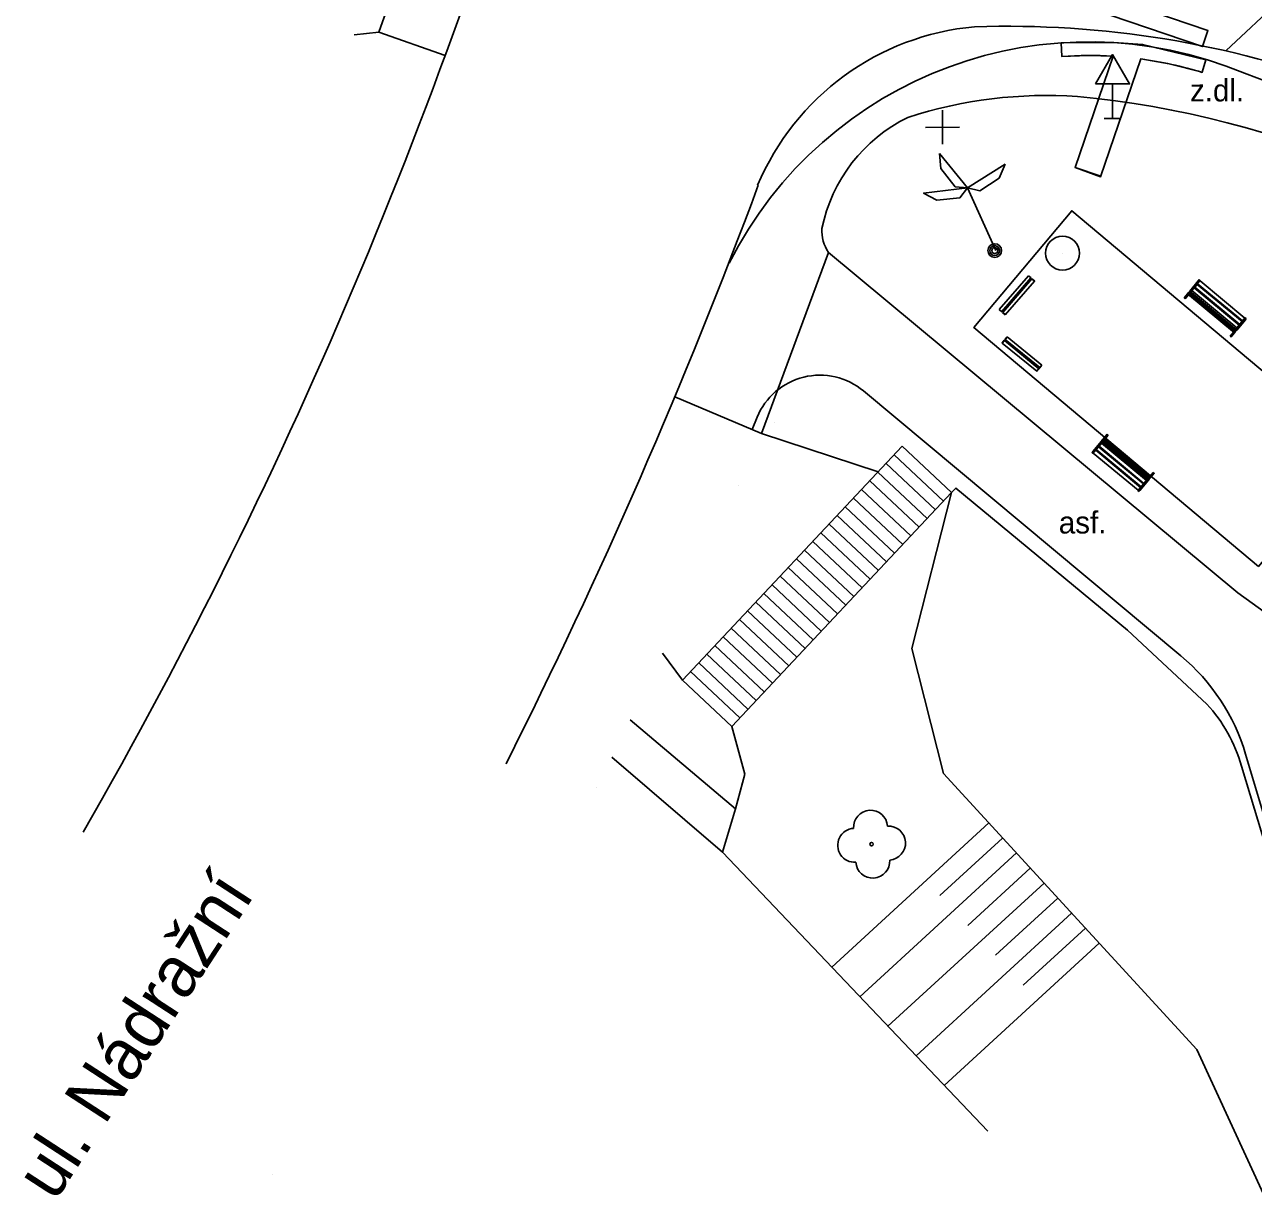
# Model space of a CAD drawing. Extents: x -438303 to -437792, y -1133191 to -1132731.
# Drawn here: x -438176.97 to -438140.8, y -1132981.26 to -1132946.7 of the extents above; entities that cross this region are included whole.
import ezdxf

# ---------------------------------------------------------------- set-up
doc = ezdxf.new("R2010")
doc.units = 0
for name, color, linetype in [('MOBILIÁŘ', 7, 'Continuous'), ('Vrstva 1', 7, 'Continuous'), ('Vrstva 10', 7, 'Continuous'), ('Vrstva 11', 7, 'Continuous'), ('Vrstva 14', 7, 'Continuous'), ('Vrstva 15', 7, 'Continuous'), ('Vrstva 22', 7, 'Continuous'), ('Vrstva 27', 7, 'Continuous'), ('Vrstva 3', 7, 'Continuous'), ('Vrstva 33', 7, 'Continuous'), ('Vrstva 34', 7, 'Continuous'), ('Vrstva 40', 7, 'Continuous'), ('Vrstva 61', 7, 'Continuous')]:
    doc.layers.add(name, color=color, linetype=linetype)

# ---------------------------------------------------------------- blocks, each defined once
blk = doc.blocks.new('A$C6CEF62CF')
at = {"layer": 'Vrstva 1'}
for p, q in [((-6549, 2350), (-6600, 2350)), ((-6600, 2350), (-6600, 2328)), ((-6600, 2328), (-6600, 1317)), ((-6549, 1317), (-6600, 1317)), ((-6600, 15), (-6600, 1026)), ((-6549, 1026), (-6600, 1026)), ((-6600, 0), (-6600, 15)), ((-6549, 0), (-6600, 0)), ((-6549, 2328), (-6549, 2351)), ((-6549, 2350), (6549, 2350)), ((-6549, 2328), (-6549, 1339)), ((-6549, 1375), (6549, 1375)), ((-6549, 1317), (-6549, 1339)), ((-6549, 1317), (6549, 1317)), ((-6549, 1026), (-6549, 1004)), ((-6549, 1026), (6549, 1026)), ((-6549, 15), (-6549, 1004)), ((-6549, 968), (6549, 968)), ((-6549, 15), (-6549, 0)), ((-6549, 0), (6549, 0)), ((-6447, 1317), (-6447, 1026)), ((-6033, 1026), (-6033, 1317)), ((6032, 1317), (6032, 1026)), ((6447, 1026), (6447, 1317)), ((6600, 2350), (6549, 2350)), ((6549, 2350), (6549, 2328)), ((6549, 2328), (6549, 1339)), ((6549, 1339), (6549, 1317)), ((6600, 1317), (6549, 1317)), ((6549, 15), (6549, 1026)), ((6600, 1026), (6549, 1026)), ((6549, 0), (6549, 15)), ((6600, 0), (6549, 0)), ((6600, 2328), (6600, 2351)), ((6600, 2328), (6600, 1339)), ((6600, 1317), (6600, 1339)), ((6600, 1026), (6600, 1004)), ((6600, 15), (6600, 1004)), ((6600, 15), (6600, 0))]:
    blk.add_line(p, q, dxfattribs=at)
blk = doc.blocks.new('A$C6FF56919')
at = {"layer": 'Vrstva 1'}
for p, q in [((-18000, 5423), (-18000, 5482)), ((-18000, 5482), (-17605, 5482)), ((-18000, 5423), (0, 5423)), ((-18000, 5108), (-18000, 5423)), ((-18000, 5108), (0, 5108)), ((-18000, 4771), (-18000, 5108)), ((-18000, 4771), (0, 4771)), ((-18000, 4707), (-18000, 4771)), ((0, 4707), (-18000, 4707)), ((-18000, 4707), (-18000, 4365)), ((-18000, 459), (-18000, 4365)), ((-18000, 4365), (0, 4365)), ((-17605, 5482), (-17605, 7031)), ((-17605, 5423), (-17605, 5482)), ((-17605, 459), (-17605, 4365)), ((-17605, 3703), (-17594, 3703)), ((-17594, 2805), (-17594, 3895)), ((-401, 3703), (-411, 3703)), ((-401, 7031), (-401, 5482)), ((0, 7031), (-401, 7031)), ((-401, 5482), (0, 5482)), ((-401, 5423), (-401, 5482)), ((-401, 459), (-401, 4365)), ((0, 5482), (0, 7031)), ((0, 5423), (0, 5482)), ((0, 5423), (0, 5108)), ((0, 5108), (0, 4771)), ((0, 4771), (0, 4707)), ((0, 4365), (0, 4707)), ((0, 459), (0, 4365)), ((-18000, 459), (-18000, 0)), ((-17605, 459), (-18000, 459)), ((-18000, 0), (-17605, 0)), ((-17605, 2907), (-17594, 2907)), ((-17605, 2901), (-17594, 2901)), ((-17605, 2410), (-17594, 2410)), ((-17605, 1608), (-17594, 1608)), ((-17605, 1608), (-17594, 1608)), ((-17605, 1106), (-17594, 1106)), ((-17605, 1106), (-17594, 1106)), ((-17605, 0), (-17605, 459)), ((-17605, 305), (-17594, 305)), ((-411, 2805), (-17594, 2805)), ((-17594, 2805), (-17594, 2762)), ((-17594, 2762), (-411, 2762)), ((-17594, 2575), (-411, 2575)), ((-17594, 1475), (-17594, 2575)), ((-17594, 1459), (-17594, 1475)), ((-17594, 1475), (-411, 1475)), ((-411, 1459), (-17594, 1459)), ((-17594, 1245), (-17594, 1256)), ((-17594, 1256), (-411, 1256)), ((-17594, 1245), (-17594, 144)), ((-411, 1245), (-17594, 1245)), ((-17594, 144), (-411, 144)), ((-9200, 2575), (-9200, 2762)), ((-9200, 1256), (-9200, 1459)), ((-8800, 1256), (-8800, 1459)), ((-8799, 2575), (-8799, 2762)), ((-401, 2907), (-411, 2907)), ((-401, 2901), (-411, 2901)), ((-411, 2762), (-411, 2805)), ((-411, 2575), (-411, 1475)), ((-401, 2410), (-411, 2410)), ((-401, 1608), (-411, 1608)), ((-401, 1608), (-411, 1608)), ((-411, 1475), (-411, 1459)), ((-411, 1256), (-411, 1245)), ((-411, 144), (-411, 1245)), ((-401, 1106), (-411, 1106)), ((-401, 1106), (-411, 1106)), ((-401, 305), (-411, 305)), ((-401, 459), (0, 459)), ((-401, 0), (-401, 459)), ((0, 0), (-401, 0)), ((0, 459), (0, 0))]:
    blk.add_line(p, q, dxfattribs=at)
for points in [[(-17605, 7031), (-18000, 7031), (-18000, 5482)], [(-17594, 3895), (-411, 3895), (-411, 2805)]]:
    blk.add_lwpolyline(points, dxfattribs=at)

msp = doc.modelspace()

# ---------------------------------------------------------------- linework, layer by layer
at = {"layer": 'Vrstva 1'}
for p, q in [((-438167.27, -1132947.001), (-438167.27, -1132947.001)), ((-438166.545, -1132946.916), (-438166.545, -1132946.916)), ((-438149.002, -1132946.761), (-438149.002, -1132946.761)), ((-438145.381, -1132946.866), (-438145.381, -1132946.866)), ((-438164.592, -1132947.612), (-438164.592, -1132947.612)), ((-438124.232, -1132954.585), (-438141.06, -1132948.127)), ((-438124.232, -1132954.585), (-438141.06, -1132948.127)), ((-438152.923, -1132948.266), (-438152.923, -1132948.266)), ((-438145.975, -1132948.81), (-438145.975, -1132948.81)), ((-438150.969, -1132949.428), (-438150.969, -1132949.428)), ((-438144.941, -1132949.462), (-438144.941, -1132949.462)), ((-438152.412, -1132950.528), (-438152.412, -1132950.528)), ((-438155.392, -1132951.428), (-438155.392, -1132951.428)), ((-438155.374, -1132951.429), (-438155.374, -1132951.429)), ((-438153.5, -1132952.702), (-438153.5, -1132952.702)), ((-438153.308, -1132953.412), (-438153.308, -1132953.412)), ((-438148.411, -1132953.352), (-438148.411, -1132953.352)), ((-438146.415, -1132953.427), (-438146.415, -1132953.427)), ((-438152.276, -1132957.484), (-438142.931, -1132965.284)), ((-438152.276, -1132957.484), (-438142.931, -1132965.284)), ((-438157.832, -1132957.657), (-438157.832, -1132957.657)), ((-438155.555, -1132958.619), (-438155.406, -1132958.257)), ((-438155.555, -1132958.619), (-438155.406, -1132958.257)), ((-438155.441, -1132958.667), (-438155.441, -1132958.667)), ((-438154.907, -1132958.401), (-438154.907, -1132958.401)), ((-438151.132, -1132959.115), (-438151.132, -1132959.115)), ((-438151.848, -1132959.865), (-438151.848, -1132959.865)), ((-438155.944, -1132960.276), (-438155.944, -1132960.276)), ((-438149.556, -1132960.347), (-438149.556, -1132960.347)), ((-438154.46, -1132962.678), (-438154.46, -1132962.678)), ((-438141.257, -1132963.425), (-438141.257, -1132963.425)), ((-438144.5, -1132964.529), (-438144.5, -1132964.529)), ((-438150.852, -1132965.072), (-438150.852, -1132965.072)), ((-438157.606, -1132965.999), (-438157.606, -1132965.999)), ((-438142.166, -1132966.704), (-438142.166, -1132966.704)), ((-438158.97, -1132967.316), (-438158.97, -1132967.316)), ((-438141.025, -1132968.181), (-438139.425, -1132973.566)), ((-438141.025, -1132968.181), (-438139.425, -1132973.566)), ((-438162.8, -1132968.465), (-438162.8, -1132968.465)), ((-438155.769, -1132968.766), (-438155.769, -1132968.766)), ((-438149.923, -1132968.747), (-438149.923, -1132968.747)), ((-438141.146, -1132968.53), (-438141.146, -1132968.53)), ((-438160.123, -1132969.168), (-438160.123, -1132969.168)), ((-438156.039, -1132969.791), (-438156.039, -1132969.791)), ((-438175.245, -1132970.477), (-438175.245, -1132970.477)), ((-438152.036, -1132970.831), (-438152.036, -1132970.831)), ((-438156.429, -1132971.063), (-438156.429, -1132971.063)), ((-438142.461, -1132976.877), (-438142.461, -1132976.877)), ((-438169.66, -1132980.558), (-438169.66, -1132980.558))]:
    msp.add_line(p, q, dxfattribs=at)
msp.add_lwpolyline([(-438146.082, -1132946.053), (-438145.921, -1132945.58), (-438142.135, -1132946.872), (-438142.297, -1132947.345)], close=True, dxfattribs=at)
msp.add_lwpolyline([(-438146.082, -1132946.053), (-438145.921, -1132945.58), (-438142.135, -1132946.872), (-438142.297, -1132947.345)], close=True, dxfattribs=at)
for centre, radius, start, end in [((-438145.642, -1132959.068), 11.861, 67.2719, 153.2336), ((-438145.642, -1132959.068), 11.861, 67.2719, 153.2336), ((-438153.557, -1132959.02), 2, 50.1489, 157.573), ((-438153.557, -1132959.02), 2, 50.1489, 157.573), ((-438146.776, -1132969.89), 6, 16.5498, 50.1489), ((-438146.776, -1132969.89), 6, 16.5498, 50.1489)]:
    msp.add_arc(centre, radius, start, end, dxfattribs=at)
at = {"layer": 'Vrstva 10'}
msp.add_line((-438134.051, -1132940.322), (-438141.608, -1132947.471), dxfattribs=at)
for centre, radius, start, end in [((-438304.501, -1132896.34), 149.008, 330.16266, 344.36721), ((-438148.044, -1132975.61), 28.865, 47.4586, 91.9024), ((-438148.315, -1132954.409), 7.679, 95.1346, 157.1625), ((-438314.418, -1132892.236), 169.703, 333.30817, 339.58563)]:
    msp.add_arc(centre, radius, start, end, dxfattribs=at)
at = {"layer": 'Vrstva 11'}
for p, q in [((-438149.211, -1132951.505), (-438150.035, -1132950.496)), ((-438150.035, -1132950.496), (-438150.001, -1132950.939)), ((-438150.001, -1132950.939), (-438149.579, -1132951.474)), ((-438149.211, -1132951.505), (-438148.109, -1132950.812)), ((-438148.109, -1132950.812), (-438148.282, -1132951.221)), ((-438148.282, -1132951.221), (-438148.853, -1132951.593)), ((-438149.579, -1132951.474), (-438149.211, -1132951.505)), ((-438148.853, -1132951.593), (-438149.211, -1132951.505))]:
    msp.add_line(p, q, dxfattribs=at)
for points in [[(-438167.27, -1132947.001), (-438166.545, -1132946.916)], [(-438166.545, -1132946.916), (-438164.592, -1132947.612)], [(-438148.38, -1132953.345), (-438149.211, -1132951.505), (-438150.504, -1132951.657), (-438150.113, -1132951.867), (-438149.435, -1132951.798), (-438149.211, -1132951.505)], [(-438155.28, -1132958.736), (-438153.308, -1132953.412)], [(-438153.308, -1132953.412), (-438141.257, -1132963.425), (-438139.214, -1132964.899)], [(-438155.28, -1132958.736), (-438157.832, -1132957.657)], [(-438155.28, -1132958.736), (-438151.84, -1132959.868)], [(-438151.132, -1132959.115), (-438157.606, -1132965.999)], [(-438151.371, -1132959.369), (-438149.92, -1132960.734)], [(-438151.132, -1132959.115), (-438149.68, -1132960.48)], [(-438151.612, -1132959.624), (-438150.16, -1132960.99)], [(-438152.091, -1132960.134), (-438150.639, -1132961.5)], [(-438151.851, -1132959.879), (-438150.4, -1132961.244)], [(-438149.68, -1132960.48), (-438156.155, -1132967.365)], [(-438152.331, -1132960.389), (-438150.879, -1132961.754)], [(-438149.68, -1132960.48), (-438149.556, -1132960.347), (-438144.5, -1132964.529), (-438142.166, -1132966.704)], [(-438152.571, -1132960.644), (-438151.12, -1132962.01)], [(-438153.05, -1132961.154), (-438151.599, -1132962.519)], [(-438152.811, -1132960.899), (-438151.359, -1132962.264)], [(-438153.29, -1132961.408), (-438151.838, -1132962.774)], [(-438153.77, -1132961.918), (-438152.318, -1132963.284)], [(-438153.53, -1132961.664), (-438152.079, -1132963.029)], [(-438154.009, -1132962.174), (-438152.558, -1132963.539)], [(-438154.25, -1132962.428), (-438152.798, -1132963.794)], [(-438154.729, -1132962.938), (-438153.277, -1132964.303)], [(-438154.489, -1132962.684), (-438153.038, -1132964.049)], [(-438154.968, -1132963.194), (-438153.517, -1132964.559)], [(-438155.448, -1132963.703), (-438153.997, -1132965.069)], [(-438155.209, -1132963.448), (-438153.757, -1132964.813)], [(-438155.688, -1132963.958), (-438154.237, -1132965.323)], [(-438156.168, -1132964.468), (-438154.717, -1132965.833)], [(-438155.928, -1132964.213), (-438154.476, -1132965.579)], [(-438156.408, -1132964.723), (-438154.956, -1132966.089)], [(-438156.647, -1132964.978), (-438155.196, -1132966.343)], [(-438158.193, -1132965.204), (-438157.606, -1132965.997)], [(-438157.127, -1132965.487), (-438155.676, -1132966.853)], [(-438156.888, -1132965.233), (-438155.436, -1132966.598)], [(-438157.367, -1132965.743), (-438155.915, -1132967.108)], [(-438157.606, -1132965.997), (-438156.155, -1132967.363)], [(-438159.143, -1132967.17), (-438156.039, -1132969.791), (-438156.429, -1132971.063), (-438159.686, -1132968.265)], [(-438156.155, -1132967.363), (-438155.769, -1132968.766), (-438156.039, -1132969.791)], [(-438141.146, -1132968.53), (-438138.807, -1132976.255), (-438138.695, -1132977.059)]]:
    msp.add_lwpolyline(points, dxfattribs=at)
for centre, radius, start, end in [((-438312.123, -1132893.412), 155.099, 339.82033, 350.92032), ((-438146.845, -1132962.268), 13.486, 86.2998, 107.8084), ((-438148.748, -1132977.434), 28.758, 48.9102, 84.4657), ((-438148.894, -1132953.648), 4.702, 116.1861, 168.3937), ((-438152.274, -1132952.75), 1.227, 177.7333, 212.5889), ((-438145.53, -1132969.782), 4.559, 15.9318, 42.4549)]:
    msp.add_arc(centre, radius, start, end, dxfattribs=at)
at = {"layer": 'Vrstva 14'}
for points in [[(-438149.68, -1132960.48), (-438150.852, -1132965.072), (-438149.923, -1132968.747), (-438142.461, -1132976.877), (-438140.436, -1132981.262)], [(-438156.429, -1132971.063), (-438148.618, -1132979.283)]]:
    msp.add_lwpolyline(points, dxfattribs=at)
at = {"layer": 'Vrstva 15'}
for p, q in [((-438146.459, -1132947.23), (-438146.436, -1132947.634)), ((-438146.459, -1132947.23), (-438146.436, -1132947.634)), ((-438144.929, -1132947.628), (-438146.046, -1132950.903)), ((-438144.929, -1132947.628), (-438146.046, -1132950.903)), ((-438144.111, -1132947.709), (-438145.294, -1132951.178)), ((-438144.111, -1132947.709), (-438145.294, -1132951.178)), ((-438142.197, -1132947.732), (-438142.304, -1132948.103)), ((-438142.197, -1132947.732), (-438142.304, -1132948.103)), ((-438146.046, -1132950.903), (-438145.288, -1132951.161)), ((-438146.046, -1132950.903), (-438145.288, -1132951.161)), ((-438148.584, -1132970.207), (-438153.208, -1132974.452)), ((-438148.178, -1132970.649), (-438150.025, -1132972.345)), ((-438147.772, -1132971.09), (-438152.382, -1132975.322)), ((-438147.366, -1132971.533), (-438149.207, -1132973.223)), ((-438146.96, -1132971.975), (-438151.555, -1132976.192)), ((-438146.555, -1132972.417), (-438148.39, -1132974.102)), ((-438146.149, -1132972.859), (-438150.728, -1132977.063)), ((-438145.743, -1132973.301), (-438147.572, -1132974.979)), ((-438145.337, -1132973.743), (-438149.902, -1132977.932))]:
    msp.add_line(p, q, dxfattribs=at)
msp.add_lwpolyline([(-438146.459, -1132947.23), (-438144.901, -1132947.227), (-438144.058, -1132947.28), (-438142.197, -1132947.732), (-438142.304, -1132948.103), (-438143.28, -1132947.854), (-438144.111, -1132947.709), (-438145.294, -1132951.178), (-438146.046, -1132950.903), (-438144.929, -1132947.628), (-438145.664, -1132947.604), (-438146.436, -1132947.634)], close=True, dxfattribs=at)
msp.add_lwpolyline([(-438146.459, -1132947.23), (-438144.901, -1132947.227), (-438144.058, -1132947.28), (-438142.197, -1132947.732), (-438142.304, -1132948.103), (-438143.28, -1132947.854), (-438144.111, -1132947.709), (-438145.294, -1132951.178), (-438146.046, -1132950.903), (-438144.929, -1132947.628), (-438145.664, -1132947.604), (-438146.436, -1132947.634)], close=True, dxfattribs=at)
for start, end in [(86.4321, 93.9733), (86.4321, 93.9733), (73.0657, 82.3234), (73.0657, 82.3234)]:
    msp.add_arc((-438145.642, -1132959.068), 11.461, start, end, dxfattribs=at)
at = {"layer": 'Vrstva 22'}
msp.add_circle((-438152.036, -1132970.831), 0.05, dxfattribs=at)
for centre, start, end in [((-438152.068, -1132970.332), 3.7524, 183.7524), ((-438152.534, -1132970.864), 93.7524, 273.7524), ((-438151.537, -1132970.799), 273.7524, 93.7524), ((-438152.003, -1132971.33), 183.7524, 3.7524)]:
    msp.add_arc(centre, 0.5, start, end, dxfattribs=at)
at = {"layer": 'Vrstva 27'}
msp.add_circle((-438146.415, -1132953.427), 0.5, dxfattribs=at)
at = {"layer": 'Vrstva 33'}
for radius in [0.2, 0.145, 0.0876]:
    msp.add_circle((-438148.411, -1132953.352), radius, dxfattribs=at)
at = {"layer": 'Vrstva 34'}
for p, q in [((-438144.943, -1132948.444), (-438144.941, -1132949.462)), ((-438145.191, -1132949.463), (-438144.691, -1132949.462))]:
    msp.add_line(p, q, dxfattribs=at)
msp.add_lwpolyline([(-438145.443, -1132948.445), (-438144.443, -1132948.443), (-438144.945, -1132947.578)], close=True, dxfattribs=at)
at = {"layer": 'Vrstva 40'}
for points in [[(-438149.029, -1132955.616), (-438140.648, -1132962.653), (-438137.763, -1132959.218), (-438146.144, -1132952.181)], [(-438146.144, -1132952.181), (-438137.763, -1132959.218), (-438140.648, -1132962.653), (-438149.029, -1132955.616)]]:
    msp.add_lwpolyline(points, close=True, dxfattribs=at)
at = {"layer": 'Vrstva 61'}
for p, q in [((-438149.954, -1132949.222), (-438149.952, -1132950.222)), ((-438150.453, -1132949.723), (-438149.453, -1132949.722))]:
    msp.add_line(p, q, dxfattribs=at)

# ---------------------------------------------------------------- block references
at = {"layer": 'MOBILIÁŘ'}
for name, p, xscale, yscale, rotation in [('A$C6CEF62CF', (-438147.673, -1132954.744), 0.00010000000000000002, 0.00010000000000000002, 49.11310687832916), ('A$C6CEF62CF', (-438147.673, -1132954.744), 0.00010000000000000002, 0.00010000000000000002, 49.11310687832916), ('A$C6FF56919', (-438142.39, -1132954.206), 0.00010000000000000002, 0.00010000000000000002, 140.33085516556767), ('A$C6CEF62CF', (-438147.682, -1132956.491), 0.00010000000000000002, 0.00010000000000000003, -39.16768156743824), ('A$C6CEF62CF', (-438147.682, -1132956.491), 0.00010000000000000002, 0.00010000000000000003, -39.16768156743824), ('A$C6FF56919', (-438145.551, -1132959.299), 9.999999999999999e-05, -9.999999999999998e-05, 140.33085515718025)]:
    msp.add_blockref(name, p, dxfattribs=dict(at, xscale=xscale, yscale=yscale, rotation=rotation))

# ---------------------------------------------------------------- texts
at = {"layer": 'Vrstva 3'}
msp.add_text('ul. Nádražní', height=1.5, rotation=56.9488, dxfattribs=at).set_placement((-438176.078, -1132981.379))
at = {"layer": 'Vrstva 40'}
for s, p in [('z.dl.', (-438142.662, -1132948.961)), ('asf.', (-438146.525, -1132961.684))]:
    msp.add_text(s, height=0.65, rotation=0.1042, dxfattribs=at).set_placement(p)

doc.saveas('drawing.dxf')
